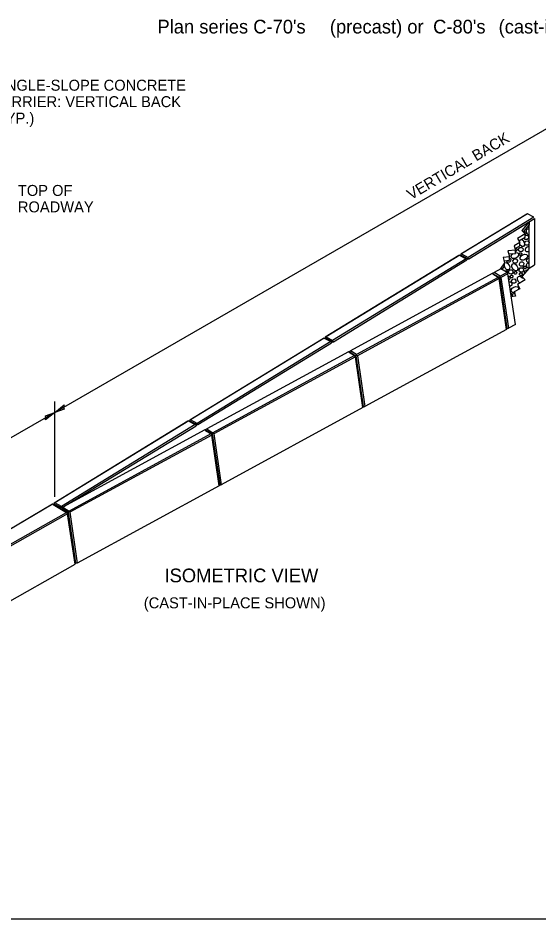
# Model space of a CAD drawing. Extents: x 99862 to 103151, y 100000 to 102076.
# Drawn here: x 101804 to 102564, y 100000 to 101314 of the extents above; entities that cross this region are included whole.
import ezdxf

# ---------------------------------------------------------------- set-up
doc = ezdxf.new("R2010")
doc.units = 0
for name, color, linetype in [('Level 1', 7, 'Continuous'), ('Level 15', 7, 'Continuous'), ('Level 2', 7, 'Continuous'), ('Level 20', 7, 'Continuous'), ('Level 25', 7, 'Continuous'), ('Level 3', 7, 'Continuous'), ('Level 41', 7, 'Continuous'), ('Level 7', 7, 'Continuous'), ('Level 8', 7, 'Continuous')]:
    doc.layers.add(name, color=color, linetype=linetype)

msp = doc.modelspace()

# ---------------------------------------------------------------- linework, layer by layer
at = {"layer": 'Level 1'}
msp.add_lwpolyline([(99862, 99999.5), (103151, 99999.5), (103151, 102075.5), (99862, 102075.5)], close=True, dxfattribs=at)
at = {"layer": 'Level 15'}
for p, q in [((103034.9, 101418.4), (101857.3, 100738.4)), ((101857.3, 100615.3), (101857.3, 100754.4)), ((101857.3, 100738.4), (101248.7, 100387))]:
    msp.add_line(p, q, dxfattribs=at)
at = {"layer": 'Level 2'}
for p, q in [((102545.7, 101028), (102449.5, 100969.2)), ((102546.9, 101028.5), (102450.8, 100969.7)), ((102556.1, 101023.2), (102460.3, 100964.5)), ((102461.3, 100962.7), (102557.2, 101021.4)), ((102556.1, 101023.2), (102546.9, 101028.5)), ((102557.2, 101021.4), (102557.2, 100954)), ((102446.8, 100967.5), (102251.9, 100848.2)), ((102448.1, 100968), (102253.2, 100848.7)), ((102446.8, 100967.5), (102447.9, 100968)), ((102448.1, 100968), (102457.5, 100962.8)), ((102449.6, 100967.9), (102448.9, 100967.5)), ((102449.5, 100969.2), (102449.2, 100967.7)), ((102449.6, 100967.9), (102449.5, 100967.2)), ((102449.6, 100969.1), (102450.8, 100969.7)), ((102449.6, 100969.1), (102449.6, 100967.9)), ((102459.2, 100962.7), (102449.6, 100967.9)), ((102450.8, 100969.7), (102460.3, 100964.5)), ((102459.2, 100962.7), (102460.3, 100963.3)), ((102460.3, 100963.3), (102460.3, 100964.5)), ((102461.3, 100962.7), (102460.3, 100963.3)), ((102457.5, 100962.8), (102262.6, 100843.6)), ((102458.6, 100962.2), (102457.5, 100962.8)), ((102458.6, 100962.2), (102459.2, 100962.7)), ((102458.6, 100962.2), (102458.6, 100961)), ((102458.6, 100961), (102458.6, 100961)), ((102549.3, 100949.2), (102557.2, 100954)), ((102495.2, 100941.1), (102288.6, 100828.6)), ((102496.3, 100940.5), (102495.2, 100941.1)), ((102504.1, 100935.6), (102495.2, 100941.1)), ((102496.3, 100940.5), (102497, 100940.9)), ((102496.3, 100940.5), (102505.4, 100934.9)), ((102497, 100942.1), (102498.1, 100942.7)), ((102497, 100940.9), (102497, 100942.1)), ((102497, 100940.9), (102506.1, 100935.3)), ((102507.9, 100948), (102498.1, 100942.7)), ((102507, 100937.2), (102498.1, 100942.7)), ((102517.1, 100942.7), (102507, 100937.2)), ((102507.1, 100935.9), (102507, 100937.2)), ((102517.1, 100942.7), (102507.9, 100948)), ((102518.4, 100940.8), (102508.2, 100935.3)), ((102518.4, 100940.8), (102517.1, 100942.7)), ((102529.5, 100867), (102518.4, 100940.8)), ((102504.1, 100935.6), (102297.5, 100823.1)), ((102505.3, 100933.7), (102298.7, 100821.2)), ((102505.2, 100934.9), (102504.1, 100935.6)), ((102505.3, 100933.7), (102505.2, 100934.9)), ((102516.1, 100859.7), (102505.3, 100933.7)), ((102506.1, 100935.3), (102505.4, 100934.9)), ((102505.4, 100934.9), (102516.2, 100860.9)), ((102507.1, 100935.9), (102506.1, 100935.3)), ((102506.1, 100935.3), (102516.9, 100861.3)), ((102508.2, 100935.3), (102507.1, 100935.9)), ((102508.2, 100935.3), (102519, 100861.3)), ((102516.1, 100859.7), (102309.5, 100747.2)), ((102516.2, 100860.9), (102516.1, 100859.7)), ((102516.9, 100861.3), (102516.2, 100860.9)), ((102516.9, 100861.3), (102519, 100861.3)), ((102529.5, 100867), (102519, 100861.3)), ((102249.1, 100846.5), (102054.3, 100727.3)), ((102250.4, 100847), (102055.5, 100727.8)), ((102249.1, 100846.5), (102250.3, 100847.1)), ((102250.4, 100847), (102259.9, 100841.9)), ((102252, 100847), (102251.3, 100846.6)), ((102251.9, 100848.2), (102251.6, 100846.7)), ((102252, 100847), (102251.8, 100846.3)), ((102252, 100848.2), (102253.2, 100848.7)), ((102252, 100848.2), (102252, 100847)), ((102261.6, 100841.7), (102252, 100847)), ((102253.2, 100848.7), (102262.6, 100843.6)), ((102259.9, 100841.9), (102065, 100722.6)), ((102260.9, 100841.3), (102259.9, 100841.9)), ((102260.9, 100841.3), (102261, 100840.1)), ((102261, 100840.1), (102261, 100840.1)), ((102261.6, 100841.7), (102262.7, 100842.3)), ((102262.7, 100842.3), (102262.6, 100843.6)), ((102263.7, 100841.7), (102262.7, 100842.3)), ((102285.7, 100827), (102079.1, 100714.5)), ((102294.6, 100821.5), (102088, 100709)), ((102295.8, 100819.6), (102089.2, 100707.1)), ((102286.8, 100826.4), (102285.7, 100827)), ((102294.6, 100821.5), (102285.7, 100827)), ((102286.8, 100826.4), (102287.5, 100826.8)), ((102286.8, 100826.4), (102295.9, 100820.8)), ((102287.5, 100828), (102288.6, 100828.6)), ((102287.5, 100826.8), (102287.5, 100828)), ((102287.5, 100826.8), (102296.6, 100821.2)), ((102297.5, 100823.1), (102288.6, 100828.6)), ((102295.8, 100820.8), (102294.6, 100821.5)), ((102295.8, 100819.6), (102295.8, 100820.8)), ((102306.6, 100745.6), (102295.8, 100819.6)), ((102296.6, 100821.2), (102295.9, 100820.8)), ((102295.9, 100820.8), (102306.7, 100746.8)), ((102297.6, 100821.8), (102296.6, 100821.2)), ((102296.6, 100821.2), (102307.4, 100747.2)), ((102297.6, 100821.8), (102297.5, 100823.1)), ((102298.7, 100821.2), (102297.6, 100821.8)), ((102298.7, 100821.2), (102309.5, 100747.2)), ((102306.6, 100745.6), (102100, 100633.1)), ((102306.7, 100746.8), (102306.6, 100745.6)), ((102307.4, 100747.2), (102306.7, 100746.8)), ((102307.4, 100747.2), (102309.5, 100747.2)), ((102054.3, 100727.3), (102054, 100725.8)), ((102054.4, 100727.2), (102054.3, 100726)), ((102054.4, 100727.2), (102055.5, 100727.8)), ((102065, 100722.6), (102055.5, 100727.8)), ((102051.5, 100725.6), (101856.3, 100606.1)), ((102052.8, 100726.1), (101857.6, 100606.6)), ((102062.3, 100720.9), (101867, 100601.4)), ((102051.5, 100725.6), (102052.7, 100726.1)), ((102052.8, 100726.1), (102062.3, 100720.9)), ((102054.3, 100726), (102053.7, 100725.6)), ((102054.3, 100726), (102054.2, 100725.3)), ((102064, 100720.8), (102054.3, 100726)), ((102063.3, 100720.3), (102062.3, 100720.9)), ((102063.3, 100720.3), (102063.4, 100719.1)), ((102063.4, 100719.1), (102063.4, 100719.1)), ((102064, 100720.8), (102065, 100721.4)), ((102065, 100721.4), (102065, 100722.6)), ((102066.1, 100720.8), (102065, 100721.4)), ((102078, 100713.9), (102079.1, 100714.5)), ((102078, 100712.7), (102078, 100713.9)), ((102079.1, 100714.5), (102088, 100709)), ((102076.2, 100712.9), (101869.2, 100600.2)), ((102085.1, 100707.4), (101878.2, 100594.7)), ((102086.3, 100705.5), (101879.4, 100592.8)), ((102077.3, 100712.3), (102076.2, 100712.9)), ((102085.1, 100707.4), (102076.2, 100712.9)), ((102077.3, 100712.3), (102086.4, 100706.7)), ((102078, 100712.7), (102087.1, 100707.1)), ((102086.3, 100706.7), (102085.1, 100707.4)), ((102086.3, 100705.5), (102086.3, 100706.7)), ((102097.1, 100631.5), (102086.3, 100705.5)), ((102087.1, 100707.1), (102086.4, 100706.7)), ((102086.4, 100706.7), (102097.2, 100632.7)), ((102088.1, 100707.7), (102087.1, 100707.1)), ((102087.1, 100707.1), (102097.9, 100633.1)), ((102088.1, 100707.7), (102088, 100709)), ((102089.2, 100707.1), (102088.1, 100707.7)), ((102089.2, 100707.1), (102100, 100633.1)), ((102097.1, 100631.5), (101890.2, 100518.8)), ((102097.2, 100632.7), (102097.1, 100631.5)), ((102097.9, 100633.1), (102097.2, 100632.7)), ((102097.9, 100633.1), (102100, 100633.1)), ((101856.3, 100606.1), (101856, 100604.6)), ((101856.4, 100606), (101857.6, 100606.6)), ((101856.4, 100606), (101856.4, 100604.8)), ((101856.4, 100604.8), (101866, 100599.6)), ((101867, 100601.4), (101857.6, 100606.6)), ((101866, 100599.6), (101867.1, 100600.2)), ((101867.1, 100600.2), (101867, 100601.4)), ((101868.1, 100599.6), (101867.1, 100600.2)), ((101868.1, 100598.4), (101868.2, 100599.6)), ((101877.2, 100592.8), (101868.1, 100598.4)), ((101868.2, 100599.6), (101869.2, 100600.2)), ((101869.2, 100600.2), (101878.2, 100594.7)), ((101878.2, 100593.4), (101877.2, 100592.8)), ((101888, 100518.7), (101877.2, 100592.8)), ((101878.2, 100593.4), (101878.2, 100594.7)), ((101879.4, 100592.8), (101878.2, 100593.4)), ((101879.4, 100592.8), (101890.2, 100518.8)), ((101683.9, 100401.9), (101886.9, 100517)), ((101890.2, 100518.8), (101888, 100518.7))]:
    msp.add_line(p, q, dxfattribs=at)
at = {"layer": 'Level 25'}
for p, q in [((102461.3, 100962.7), (102549.3, 101016.5)), ((102549.3, 101016.5), (102549.3, 101011.6)), ((102549.3, 100949.2), (102549.3, 101016.5)), ((102263.7, 100841.7), (102458.6, 100961)), ((102458.6, 100961), (102458.6, 100961)), ((102459.2, 100962.7), (102461.3, 100962.7)), ((102513.4, 100956.6), (102506.9, 100947.5)), ((102497, 100940), (102497, 100940.9)), ((102066.1, 100720.8), (102261, 100840.1)), ((102260.9, 100841.3), (102261.6, 100841.7)), ((102261, 100840.1), (102261, 100840.1)), ((102261.6, 100841.7), (102263.7, 100841.7)), ((102287.5, 100825.9), (102287.5, 100826.8)), ((101868.1, 100599.6), (102063.4, 100719.1)), ((102063.3, 100720.3), (102064, 100720.8)), ((102064, 100720.8), (102066.1, 100720.8)), ((102077.3, 100712.3), (102078, 100712.7)), ((102078, 100711.8), (102078, 100712.7))]:
    msp.add_line(p, q, dxfattribs=at)
at = {"layer": 'Level 3'}
for p, q in [((101653.5, 100486.8), (101852.8, 100604)), ((101854.1, 100604.5), (101654.8, 100487.3)), ((101854, 100604.6), (101852.8, 100604)), ((101874.6, 100592.7), (101854.1, 100604.5)), ((101856.4, 100604.8), (101855, 100604)), ((101856.4, 100604.8), (101855, 100604)), ((101855, 100604), (101874.6, 100592.7)), ((101866, 100599.6), (101856.4, 100604.8)), ((101868.1, 100599.6), (101866, 100599.6)), ((101868.1, 100599.6), (101866, 100599.6)), ((101868.1, 100599.6), (101868.2, 100599.6)), ((101868.1, 100598.4), (101868.2, 100599.6)), ((101868.2, 100599.6), (101868.1, 100599.6)), ((101877.2, 100592.8), (101868.1, 100598.4)), ((101671.5, 100477.6), (101874.6, 100592.7)), ((101875.8, 100590.8), (101672.8, 100475.7)), ((101875.7, 100592), (101874.6, 100592.7)), ((101874.6, 100592.7), (101875.7, 100592)), ((101875.8, 100590.8), (101875.7, 100592)), ((101875.8, 100592), (101875.7, 100592)), ((101875.7, 100592), (101875.8, 100592)), ((101875.8, 100592), (101887, 100518.1)), ((101875.8, 100592), (101887, 100518.1)), ((101886.9, 100517), (101875.8, 100590.8)), ((101888, 100518.7), (101877.2, 100592.8)), ((101886.9, 100517), (101887, 100518.1)), ((101887, 100518.1), (101888, 100518.7))]:
    msp.add_line(p, q, dxfattribs=at)
at = {"layer": 'Level 41'}
for p, q in [((102540.8, 101001.8), (102549.3, 101011.6)), ((102534.3, 100988.8), (102543.3, 100994.3)), ((102543.3, 100994.3), (102543.3, 100999.2)), ((102528.7, 100977.5), (102535.5, 100981.4)), ((102535.5, 100981.4), (102535.5, 100986.3)), ((102519.5, 100969.7), (102529.2, 100970.6)), ((102520.6, 100960.6), (102520.6, 100965.5)), ((102529.2, 100970.6), (102529.2, 100975.5)), ((102509.9, 100946.9), (102513.4, 100951.7)), ((102512.6, 100959.9), (102520.6, 100960.6)), ((102513.4, 100951.7), (102513.4, 100956.6))]:
    msp.add_line(p, q, dxfattribs=at)
for points in [[(102549.3, 101016.5), (102538.6, 101004.1), (102543.3, 100999.2), (102532.4, 100992.5), (102535.5, 100986.3)], [(102535.5, 100986.3), (102527.6, 100981.8), (102529.2, 100975.5), (102518.3, 100974.5), (102520.6, 100965.5), (102511.4, 100964.7), (102513.4, 100956.6)], [(102549.3, 100949.2), (102538.6, 100936.7), (102543.3, 100931.8), (102532.4, 100925.1), (102535.5, 100919)], [(102535.5, 100919), (102527.6, 100914.4), (102529.2, 100908.1), (102523.4, 100907.6)]]:
    msp.add_lwpolyline(points, dxfattribs=at)
at = {"layer": 'Level 7'}
for p, q in [((102514.5, 100945.1), (102516.9, 100945.5)), ((102542.9, 100942), (102542.1, 100943.2))]:
    msp.add_line(p, q, dxfattribs=at)
for points in [[(102549.3, 100996.4), (102547.1, 100998.2), (102545.4, 101001.5), (102545.3, 101004.7), (102546.6, 101006.5), (102549.1, 101006.6)], [(102549.3, 101008.2), (102547.9, 101008.3), (102547.1, 101009.1)], [(102538.1, 100991.1), (102540, 100990), (102541.3, 100988.3)], [(102541.5, 101001.1), (102542.1, 101001.8), (102543.7, 101001.9), (102544.9, 101000.7), (102544.7, 100999), (102543.7, 100998.2), (102543.3, 100998.2)], [(102543.3, 100996.4), (102543.6, 100996.8), (102546.4, 100997), (102548.4, 100995), (102548.1, 100992.2), (102546.4, 100990.7), (102543.6, 100990.9), (102542.3, 100992.2), (102542.1, 100993.5)], [(102530.1, 100978.2), (102531.2, 100977.2), (102531.2, 100974.7), (102530, 100973.2)], [(102533.8, 100976.5), (102535.6, 100979), (102538.4, 100979.2), (102540.3, 100977.2), (102540, 100974.4), (102538.3, 100972.9), (102535.5, 100973.1), (102534.2, 100974.4), (102533.8, 100976.5)], [(102541.2, 100988.5), (102542.5, 100985.2), (102542.2, 100982.2), (102540.9, 100980.8), (102538.4, 100980.8), (102535.7, 100983), (102535.5, 100983.3)], [(102542.7, 100986.2), (102544.4, 100988.6), (102547.2, 100988.8), (102549.1, 100986.8), (102548.9, 100984), (102547.1, 100982.5), (102544.4, 100982.7), (102543.1, 100984), (102542.7, 100986.2)], [(102549.3, 100973.3), (102548.8, 100973), (102545.6, 100973), (102543.8, 100974.2), (102543.7, 100976.7), (102545.1, 100979), (102546.7, 100980.3)], [(102546.6, 100980.2), (102549.3, 100981.3)], [(102520.6, 100963.9), (102522.5, 100961.9), (102522.2, 100959.1), (102520.5, 100957.7), (102517.7, 100957.9), (102516.4, 100959.1), (102516.2, 100960.3)], [(102529.4, 100971.7), (102532.4, 100971.5), (102533.8, 100970.1), (102533.8, 100967.7), (102531.6, 100964.9), (102528.3, 100963.2), (102525.1, 100963.2), (102523.3, 100964.4), (102523.1, 100967), (102524.6, 100969.2), (102525.8, 100970.2)], [(102534.6, 100969.9), (102535.7, 100971.4), (102537.3, 100971.5), (102538.5, 100970.3), (102538.3, 100968.6), (102537.3, 100967.8), (102535.6, 100967.9), (102534.9, 100968.6), (102534.6, 100969.9)], [(102539.1, 100968), (102542.4, 100969.3), (102545.4, 100969.1), (102546.8, 100967.7), (102546.8, 100965.3), (102544.6, 100962.5), (102541.3, 100960.8), (102538.1, 100960.8), (102536.3, 100962), (102536.2, 100964.5), (102537.6, 100966.8), (102539.3, 100968.1)], [(102545.4, 100960.8), (102547.2, 100963.3), (102549.3, 100963.4)], [(102519.7, 100954.2), (102521, 100950.9), (102520.7, 100947.9), (102519.3, 100946.5), (102516.9, 100946.5), (102515.3, 100947.7), (102514.1, 100949.5), (102513.4, 100951.7)], [(102513.7, 100957), (102516.2, 100957.2), (102518.4, 100955.7), (102519.7, 100954.1)], [(102531.4, 100952.6), (102532.7, 100949.3), (102532.5, 100946.3), (102531.1, 100944.9), (102528.7, 100944.9), (102525.9, 100947.1), (102524.2, 100950.5), (102524.2, 100953.6), (102525.4, 100955.4), (102528, 100955.6), (102530.2, 100954.1), (102531.5, 100952.5)], [(102525.6, 100959.8), (102527.3, 100962.2), (102530.1, 100962.4), (102532.1, 100960.4), (102531.8, 100957.6), (102530.1, 100956.1), (102527.3, 100956.3), (102526, 100957.6), (102525.6, 100959.8)], [(102535, 100955.5), (102536.7, 100958), (102539.5, 100958.2), (102541.5, 100956.2), (102541.2, 100953.3), (102539.5, 100951.9), (102536.7, 100952.1), (102535.4, 100953.4), (102535, 100955.5)], [(102541, 100950.4), (102542.1, 100951.9), (102543.7, 100952), (102544.9, 100950.8), (102544.7, 100949.1), (102543.7, 100948.3), (102542, 100948.4), (102541.3, 100949.1), (102541, 100950.4)], [(102547.6, 100948.9), (102546.3, 100950.2), (102545.2, 100953.2), (102545.8, 100955.3), (102548.1, 100956.3), (102549.3, 100956)], [(102549.3, 100957.3), (102547.2, 100957.4), (102545.9, 100958.7), (102545.4, 100960.8)], [(102516.9, 100945.5), (102518.5, 100943.8), (102518.2, 100941), (102517.7, 100940.5)], [(102519.1, 100937.2), (102519.8, 100937.1), (102521.3, 100935.8), (102521.2, 100933.3), (102520, 100931.7)], [(102519.2, 100943.9), (102521, 100946.4), (102523.8, 100946.5), (102525.7, 100944.5), (102525.4, 100941.7), (102523.7, 100940.3), (102520.9, 100940.5), (102519.6, 100941.7), (102519.2, 100943.9)], [(102521.8, 100937.1), (102522.8, 100938.6), (102524.5, 100938.7), (102525.7, 100937.4), (102525.5, 100935.8), (102524.5, 100934.9), (102522.8, 100935), (102522, 100935.8), (102521.8, 100937.1)], [(102527.2, 100942.3), (102528.2, 100943.8), (102529.9, 100943.9), (102531.1, 100942.7), (102530.9, 100941), (102529.9, 100940.1), (102528.2, 100940.3), (102527.4, 100941), (102527.2, 100942.3)], [(102535.8, 100927.3), (102534, 100928.7), (102532.3, 100932.1), (102532.2, 100935.2), (102533.5, 100937), (102536, 100937.2), (102538.3, 100935.7), (102539.6, 100934.1)], [(102534.5, 100946.9), (102536.3, 100949.4), (102539, 100949.5), (102541, 100947.5), (102540.7, 100944.7), (102539, 100943.3), (102536.2, 100943.5), (102534.9, 100944.7), (102534.5, 100946.9)], [(102535.2, 100940.5), (102536.2, 100942), (102537.9, 100942.1), (102539.1, 100940.9), (102538.9, 100939.2), (102537.9, 100938.3), (102536.2, 100938.5), (102535.4, 100939.2), (102535.2, 100940.5)], [(102542.1, 100943.2), (102543.3, 100946), (102546, 100946.7), (102546.9, 100946.1)], [(102520.1, 100929), (102522.2, 100929.1), (102524.1, 100927.1), (102523.8, 100924.3), (102522.1, 100922.8), (102521, 100922.9)], [(102523.5, 100930.5), (102525.3, 100933), (102528.1, 100933.2), (102530, 100931.2), (102529.7, 100928.3), (102528, 100926.9), (102525.2, 100927.1), (102524, 100928.4), (102523.5, 100930.5)], [(102520.8, 100919.5), (102520.9, 100919.4), (102520.8, 100919.3)], [(102523, 100912.7), (102523.7, 100912), (102523.5, 100909.8)], [(102528.7, 100913.8), (102528.3, 100913.6), (102525.1, 100913.5), (102523.3, 100914.8), (102523.1, 100917.3), (102524.6, 100919.6), (102526.2, 100920.9)], [(102524.8, 100909.8), (102526.5, 100912.3), (102528.3, 100912.4)], [(102526.1, 100920.8), (102529.4, 100922.1), (102532.4, 100921.8), (102533.8, 100920.5), (102533.8, 100919)], [(102534.7, 100919.5), (102534.6, 100920)], [(102525.7, 100907.2), (102525.3, 100907.7), (102524.9, 100909.8)]]:
    msp.add_lwpolyline(points, dxfattribs=at)
at = {"layer": 'Level 8'}
for points in [[(101857.3, 100738.4), (101870.9, 100749.4), (101870.3, 100745.9), (101870.9, 100743.2)], [(101857.3, 100738.4), (101843.7, 100727.5), (101844.3, 100730.9), (101843.7, 100733.6)]]:
    msp.add_lwpolyline(points, close=True, dxfattribs=at)

# ---------------------------------------------------------------- texts
at = {"layer": 'Level 20'}
for s, height, p in [("Plan series C-70's", 20, (102007.1, 101291.4)), ('(precast) or ', 20, (102258.6, 101291.4)), ("C-80's ", 20, (102409.2, 101291.4)), ('(cast-in-place).', 20, (102504.7, 101291.4)), ('SINGLE-SLOPE CONCRETE', 16, (101765.7, 101207.9)), ('BARRIER: VERTICAL BACK', 16, (101765.7, 101183.9)), ('(TYP.)', 16, (101765.7, 101159.9)), ('TOP OF', 16, (101803.5, 101054.4)), ('ROADWAY', 16, (101803.5, 101030.4)), ('ISOMETRIC VIEW', 20, (102017.4, 100490.7)), ('(CAST-IN-PLACE SHOWN)', 16, (101987.2, 100452.7))]:
    msp.add_text(s, height=height, dxfattribs=at).set_placement(p)
msp.add_text('VERTICAL BACK', height=16, rotation=30.6936, dxfattribs=at).set_placement((102377, 101048.1))

doc.saveas('drawing.dxf')
